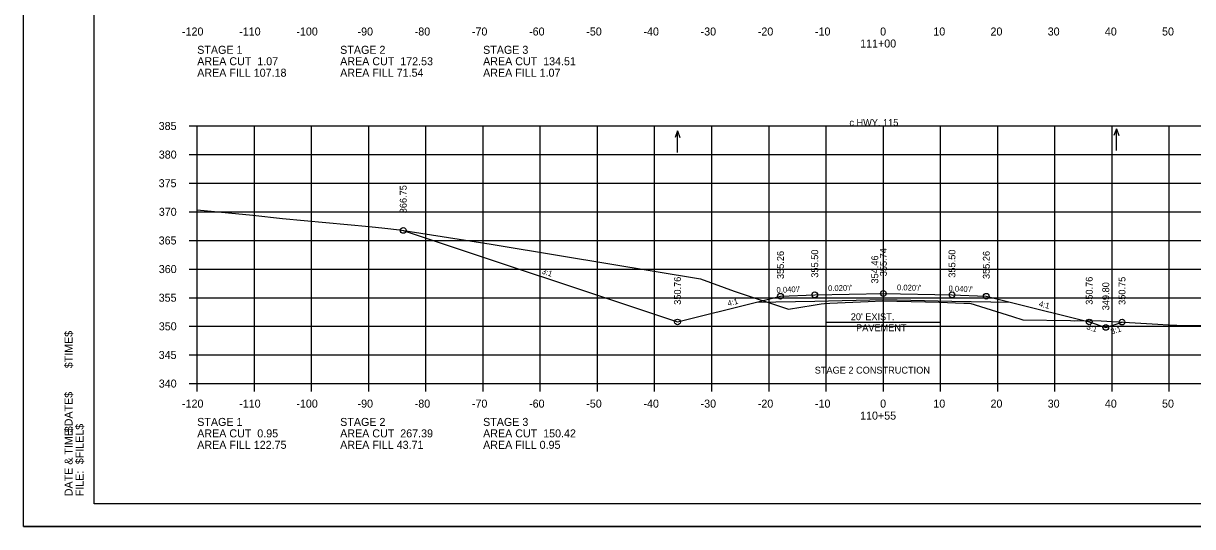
# Model space of a CAD drawing. Extents: x 1630712 to 1632516, y 782146 to 785403.
# Drawn here: x 1632182.6 to 1632387, y 784336.6 to 784424.5 of the extents above; entities that cross this region are included whole.
import ezdxf

# ---------------------------------------------------------------- set-up
doc = ezdxf.new("R2010")
doc.units = 0
for name, color, linetype in [('Default', 7, 'Continuous'), ('Notes', 7, 'Continuous'), ('R_Alt Surface', 7, 'Continuous'), ('R_Axis', 7, 'Continuous'), ('R_Axis Annot', 7, 'Continuous'), ('R_Border', 7, 'Continuous'), ('R_Exist Surface', 7, 'Continuous'), ('R_Fin Surface', 7, 'Continuous'), ('R_Grid', 7, 'Continuous'), ('R_No Plot', 7, 'Continuous'), ('R_Water Annot', 7, 'Continuous'), ('R_Xsect Elev', 7, 'Continuous'), ('R_Xsect Slope', 7, 'Continuous')]:
    doc.layers.add(name, color=color, linetype=linetype)

msp = doc.modelspace()

# ---------------------------------------------------------------- linework, layer by layer
at = {"layer": 'Notes'}
for p, q in [((1632322.96, 784370.64), (1632322.96, 784374.04)), ((1632342.96, 784370.64), (1632342.96, 784374.04)), ((1632322.96, 784372.34), (1632342.96, 784372.34))]:
    msp.add_line(p, q, dxfattribs=at)
at = {"layer": 'R_Alt Surface'}
msp.add_lwpolyline([(1632310.78, 784375.85), (1632320.96, 784376.05), (1632332.96, 784376.29), (1632344.96, 784376.05), (1632355.15, 784375.85)], dxfattribs=at)
at = {"layer": 'R_Axis'}
for p, q in [((1632211.56, 784406.63), (1632212.96, 784406.63)), ((1632212.96, 784361.63), (1632212.96, 784406.63)), ((1632211.56, 784401.63), (1632212.96, 784401.63)), ((1632211.56, 784396.63), (1632212.96, 784396.63)), ((1632211.56, 784391.63), (1632212.96, 784391.63)), ((1632211.56, 784386.63), (1632212.96, 784386.63)), ((1632211.56, 784381.63), (1632212.96, 784381.63)), ((1632211.56, 784376.63), (1632212.96, 784376.63)), ((1632211.56, 784371.63), (1632212.96, 784371.63)), ((1632211.56, 784366.63), (1632212.96, 784366.63)), ((1632211.56, 784361.63), (1632212.96, 784361.63)), ((1632212.96, 784361.63), (1632492.96, 784361.63)), ((1632212.96, 784360.23), (1632212.96, 784361.63)), ((1632222.96, 784360.23), (1632222.96, 784361.63)), ((1632232.96, 784360.23), (1632232.96, 784361.63)), ((1632242.96, 784360.23), (1632242.96, 784361.63)), ((1632252.96, 784360.23), (1632252.96, 784361.63)), ((1632262.96, 784360.23), (1632262.96, 784361.63)), ((1632272.96, 784360.23), (1632272.96, 784361.63)), ((1632282.96, 784360.23), (1632282.96, 784361.63)), ((1632292.96, 784360.23), (1632292.96, 784361.63)), ((1632302.96, 784360.23), (1632302.96, 784361.63)), ((1632312.96, 784360.23), (1632312.96, 784361.63)), ((1632322.96, 784360.23), (1632322.96, 784361.63)), ((1632332.96, 784360.23), (1632332.96, 784361.63)), ((1632342.96, 784360.23), (1632342.96, 784361.63)), ((1632352.96, 784360.23), (1632352.96, 784361.63)), ((1632362.96, 784360.23), (1632362.96, 784361.63)), ((1632372.96, 784360.23), (1632372.96, 784361.63)), ((1632382.96, 784360.23), (1632382.96, 784361.63))]:
    msp.add_line(p, q, dxfattribs=at)
at = {"layer": 'R_Border'}
for p, q in [((1632194.96, 784340.63), (1632194.96, 784546.09)), ((1632511.14, 784340.63), (1632194.96, 784340.63))]:
    msp.add_line(p, q, dxfattribs=at)
at = {"layer": 'R_Exist Surface'}
msp.add_lwpolyline([(1632212.96, 784392), (1632222.66, 784391.06), (1632227.9, 784390.49), (1632243.04, 784389.06), (1632245.77, 784388.76), (1632248.35, 784388.48), (1632264.37, 784385.99), (1632276.64, 784383.92), (1632300.99, 784379.95), (1632306.85, 784377.8), (1632316.36, 784374.64), (1632320.71, 784375.32), (1632322.08, 784375.55), (1632322.66, 784375.61), (1632323.62, 784375.7), (1632330.33, 784375.99), (1632332.82, 784376.1), (1632340.34, 784375.91), (1632342.73, 784375.85), (1632347.05, 784375.7), (1632348.11, 784375.65), (1632355.53, 784373.32), (1632357.34, 784372.76), (1632365.66, 784372.63), (1632366.37, 784372.61), (1632366.83, 784372.64), (1632371.07, 784372.59), (1632380.95, 784372.01), (1632382.77, 784371.89), (1632384.31, 784371.85), (1632396.09, 784371.76)], dxfattribs=at)
at = {"layer": 'R_Fin Surface'}
msp.add_lwpolyline([(1632248.99, 784388.38), (1632296.96, 784372.39), (1632310.78, 784375.85), (1632314.96, 784376.89), (1632320.96, 784377.13), (1632332.96, 784377.37), (1632344.96, 784377.13), (1632350.96, 784376.89), (1632355.15, 784375.85), (1632368.96, 784372.39), (1632371.86, 784371.43), (1632374.7, 784372.38)], dxfattribs=at)
at = {"layer": 'R_Grid'}
for p, q in [((1632212.96, 784406.63), (1632492.96, 784406.63)), ((1632212.96, 784361.63), (1632212.96, 784406.63)), ((1632222.96, 784361.63), (1632222.96, 784406.63)), ((1632232.96, 784361.63), (1632232.96, 784406.63)), ((1632242.96, 784361.63), (1632242.96, 784406.63)), ((1632252.96, 784361.63), (1632252.96, 784406.63)), ((1632262.96, 784361.63), (1632262.96, 784406.63)), ((1632272.96, 784361.63), (1632272.96, 784406.63)), ((1632282.96, 784361.63), (1632282.96, 784406.63)), ((1632292.96, 784361.63), (1632292.96, 784406.63)), ((1632302.96, 784361.63), (1632302.96, 784406.63)), ((1632312.96, 784361.63), (1632312.96, 784406.63)), ((1632322.96, 784361.63), (1632322.96, 784406.63)), ((1632332.96, 784361.63), (1632332.96, 784406.63)), ((1632342.96, 784361.63), (1632342.96, 784406.63)), ((1632352.96, 784361.63), (1632352.96, 784406.63)), ((1632362.96, 784361.63), (1632362.96, 784406.63)), ((1632372.96, 784361.63), (1632372.96, 784406.63)), ((1632382.96, 784361.63), (1632382.96, 784406.63)), ((1632212.96, 784401.63), (1632492.96, 784401.63)), ((1632212.96, 784396.63), (1632492.96, 784396.63)), ((1632212.96, 784391.63), (1632492.96, 784391.63)), ((1632212.96, 784386.63), (1632492.96, 784386.63)), ((1632212.96, 784381.63), (1632492.96, 784381.63)), ((1632212.96, 784376.63), (1632492.96, 784376.63)), ((1632212.96, 784371.63), (1632492.96, 784371.63)), ((1632212.96, 784366.63), (1632492.96, 784366.63)), ((1632212.96, 784361.63), (1632492.96, 784361.63))]:
    msp.add_line(p, q, dxfattribs=at)
at = {"layer": 'R_No Plot'}
msp.add_line((1632182.56, 784336.65), (1632515.9, 784336.65), dxfattribs=at)
msp.add_lwpolyline([(1632182.56, 784549.99), (1632515.9, 784549.99), (1632515.9, 784336.65), (1632182.56, 784336.65)], close=True, dxfattribs=at)
for centre in [(1632248.99, 784388.38), (1632314.96, 784376.89), (1632320.96, 784377.13), (1632332.96, 784377.37), (1632344.96, 784377.13), (1632350.96, 784376.89), (1632296.96, 784372.39), (1632296.96, 784372.39), (1632368.96, 784372.39), (1632371.86, 784371.43), (1632374.7, 784372.38)]:
    msp.add_circle(centre, 0.5, dxfattribs=at)
at = {"layer": 'R_Water Annot'}
for p, q in [((1632296.96, 784405.77), (1632296.54, 784404.62)), ((1632296.96, 784402), (1632296.96, 784405.77)), ((1632296.96, 784405.77), (1632297.38, 784404.62)), ((1632373.71, 784406.1), (1632373.29, 784404.95)), ((1632373.71, 784402.33), (1632373.71, 784406.1)), ((1632373.71, 784406.1), (1632374.13, 784404.95))]:
    msp.add_line(p, q, dxfattribs=at)

# ---------------------------------------------------------------- texts
at = {"layer": 'Default'}
for s, height, p in [('$TIME$', 1.397, (1632191.16, 784364.3)), ('$DATE$', 1.397, (1632191.16, 784353.13)), ('DATE & TIME:', 1.3968, (1632191.16, 784341.95)), ('$FILEL$', 1.397, (1632193.08, 784347.54)), ('FILE: ', 1.397, (1632193.08, 784341.95))]:
    msp.add_text(s, height=height, rotation=90, dxfattribs=at).set_placement(p)
at = {"layer": 'Notes'}
for s, p in [('c HWY. 115', (1632327.02, 784406.63)), ("20' EXIST.", (1632327.26, 784372.7)), ('PAVEMENT', (1632328.19, 784370.78)), ('STAGE 2 CONSTRUCTION', (1632320.96, 784363.37))]:
    msp.add_text(s, height=1.2, dxfattribs=at).set_placement(p)
at = {"layer": 'R_Axis'}
msp.add_text('-', height=0.0001, dxfattribs=at).set_placement((1632212.96, 784361.63))
at = {"layer": 'R_Axis Annot'}
for s, p in [('-120', (1632210.3, 784422.43)), ('-110', (1632220.3, 784422.43)), ('-100', (1632230.3, 784422.43)), ('-90', (1632241, 784422.43)), ('-80', (1632251, 784422.43)), ('-70', (1632261, 784422.43)), ('-60', (1632271, 784422.43)), ('-50', (1632281, 784422.43)), ('-40', (1632291, 784422.43)), ('-30', (1632301, 784422.43)), ('-20', (1632311, 784422.43)), ('-10', (1632321, 784422.43)), ('0', (1632332.4, 784422.43)), ('10', (1632341.7, 784422.43)), ('20', (1632351.7, 784422.43)), ('30', (1632361.7, 784422.43)), ('40', (1632371.7, 784422.43)), ('50', (1632381.7, 784422.43)), ('111+00', (1632328.9, 784420.33)), ('STAGE 1', (1632212.96, 784419.23)), ('STAGE 2', (1632237.96, 784419.23)), ('STAGE 3', (1632262.96, 784419.23)), ('AREA CUT  1.07', (1632212.96, 784417.23)), ('AREA CUT  172.53', (1632237.96, 784417.23)), ('AREA CUT  134.51', (1632262.96, 784417.23)), ('AREA FILL 107.18', (1632212.96, 784415.23)), ('AREA FILL 71.54', (1632237.96, 784415.23)), ('AREA FILL 1.07', (1632262.96, 784415.23)), ('385', (1632206.22, 784405.93)), ('380', (1632206.24, 784400.93)), ('375', (1632206.22, 784395.93)), ('370', (1632206.24, 784390.93)), ('365', (1632206.22, 784385.93)), ('360', (1632206.24, 784380.93)), ('355', (1632206.22, 784375.93)), ('350', (1632206.24, 784370.93)), ('345', (1632206.22, 784365.93)), ('340', (1632206.24, 784360.93)), ('-120', (1632210.3, 784357.43)), ('-110', (1632220.3, 784357.43)), ('-100', (1632230.3, 784357.43)), ('-90', (1632241, 784357.43)), ('-80', (1632251, 784357.43)), ('-70', (1632261, 784357.43)), ('-60', (1632271, 784357.43)), ('-50', (1632281, 784357.43)), ('-40', (1632291, 784357.43)), ('-30', (1632301, 784357.43)), ('-20', (1632311, 784357.43)), ('-10', (1632321, 784357.43)), ('0', (1632332.4, 784357.43)), ('10', (1632341.7, 784357.43)), ('20', (1632351.7, 784357.43)), ('30', (1632361.7, 784357.43)), ('40', (1632371.7, 784357.43)), ('50', (1632381.7, 784357.43)), ('STAGE 1', (1632212.96, 784354.23)), ('STAGE 2', (1632237.96, 784354.23)), ('STAGE 3', (1632262.96, 784354.23)), ('110+55', (1632328.89, 784355.33)), ('AREA CUT  0.95', (1632212.96, 784352.23)), ('AREA CUT  267.39', (1632237.96, 784352.23)), ('AREA CUT  150.42', (1632262.96, 784352.23)), ('AREA FILL 122.75', (1632212.96, 784350.23)), ('AREA FILL 43.71', (1632237.96, 784350.23)), ('AREA FILL 0.95', (1632262.96, 784350.23))]:
    msp.add_text(s, height=1.4, dxfattribs=at).set_placement(p)
at = {"layer": 'R_Xsect Elev'}
for s, p in [('366.75', (1632249.59, 784391.38)), ('355.26', (1632315.56, 784379.89)), ('355.50', (1632321.56, 784380.13)), ('355.74', (1632333.56, 784380.37)), ('355.50', (1632345.56, 784380.13)), ('355.26', (1632351.56, 784379.89)), ('354.46', (1632332.06, 784379.1)), ('350.76', (1632297.56, 784375.39)), ('350.76', (1632369.56, 784375.39)), ('350.75', (1632375.3, 784375.38)), ('349.80', (1632372.46, 784374.43))]:
    msp.add_text(s, height=1.2, rotation=90, dxfattribs=at).set_placement(p)
at = {"layer": 'R_Xsect Slope'}
for s, rotation, p in [('3:1', 341.5651, (1632273.13, 784380.86)), ("0.040'/'", 2.2906, (1632314.29, 784377.47)), ("0.020'/'", 1.1458, (1632323.3, 784377.78)), ("0.020'/'", 358.8542, (1632335.33, 784377.93)), ("0.040'/'", 357.7094, (1632344.34, 784377.76)), ('4:1', 14.0362, (1632305.84, 784375.13)), ('4:1', 345.9638, (1632360.09, 784375.13)), ('3:1', 341.5651, (1632368.41, 784371.16)), ('3:1', 18.4349, (1632372.91, 784370.19))]:
    msp.add_text(s, height=1, rotation=rotation, dxfattribs=at).set_placement(p)

doc.saveas('drawing.dxf')
